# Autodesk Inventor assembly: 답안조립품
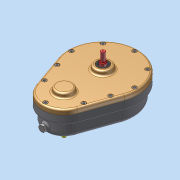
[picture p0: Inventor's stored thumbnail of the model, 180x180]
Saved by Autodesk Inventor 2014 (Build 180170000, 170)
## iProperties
Created: 2025-02
Part Number: 답안조립품
Document SubType Name: Assembly
Designer: dg
Mass: 1846.66 g
Surface Area: 1657.69 cm^2
Volume: 424.643 cm^3
Density: 4.34873 g/cm^3
Author: dg
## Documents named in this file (13)
- C:\Users\dg\Desktop\650203V1009\답안조립품.iam
- C:\Users\dg\Documents\Inventor\본체.ipt
- C:\Users\dg\Desktop\650203V1009\가져온 구성요소\상단 축\상단 축.ipt
- C:\Users\dg\Desktop\650203V1009\가져온 구성요소\스퍼기어A\스퍼기어A.ipt
- C:\Users\dg\Desktop\650203V1009\가져온 구성요소\오일리스 부시\오일리스 부시.ipt
- C:\Users\dg\Desktop\650203V1009\가져온 구성요소\평행키 5x5x12\평행키 5x5x12.ipt
- C:\Users\dg\Desktop\650203V1009\가져온 구성요소\스퍼기어B\스퍼기어B.ipt
- C:\Users\dg\Desktop\650203V1009\가져온 구성요소\하단 축\하단 축.ipt
- C:\Users\dg\Desktop\650203V1009\가져온 구성요소\가스켓\가스켓.ipt
- C:\Users\dg\Desktop\650203V1009\가져온 구성요소\커버\커버.ipt
- C:\Users\dg\Desktop\650203V1009\가져온 구성요소\육각 소켓 머리 볼트 M4x10\육각 소켓 머리 볼트 M4x10.ipt
- C:\Users\dg\Desktop\650203V1009\가져온 구성요소\오일 실 10 20 4\오일 실 10 20 4.ipt
- C:\Users\dg\Desktop\650203V1009\가져온 구성요소\육각 머리 볼트  M6x0.75x6\육각 머리 볼트  M6x0.75x6.ipt
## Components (2 placed, 2 different names)
1. 하단 축:1
2. 가스켓:1
